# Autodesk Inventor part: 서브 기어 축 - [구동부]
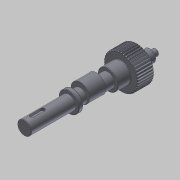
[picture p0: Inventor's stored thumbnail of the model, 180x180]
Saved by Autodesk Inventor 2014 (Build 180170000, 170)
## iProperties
Created: 2018-12
Part Number: 서브 기어 축 - [구동부]
Material: 강철, 연강
Document SubType Name: Modeling
Designer: mduedu
Categories: <?xml version="1.0" encoding="UTF-16"?> <MemberInstance><Categories><FamilyTemplate><FamilyTemplateParameter ValueType="xs:double" Id="1" ObjectReferenceKey="da
Density: 7.86 g/cm^3
Appearance: Steel
Mass: 514.759 g
Surface Area: 160.366 cm^2
Volume: 65.491 cm^3
Author: mduedu
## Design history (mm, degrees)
sketch "Sketch1"
  geometry: C1 r 21.3 at (0, 0)
  constraints: 1 centre point
  dimensions: "d0" = 42.6 diameter of C1 (= da_da)
extrude "Extrusion1" new body sketch "Sketch1" distance "d1" = 20 (= da_b); taper "d2" = 0 deg
workplane "Work Plane2"
sketch "Sketch2"
  geometry: C1 r 21.3 at (0, 0) reference; C2 r 20.5 at (0, 0)
  constraints: 1 centre point, 1 coincident
  dimensions: "d3" = 41 diameter of C2 (= da_dw)
feature "피치 지름" sketch "Sketch2" dims "d4" = 10, "d5" = 0
workplane "Work Plane8"
workplane "Work Plane9"
chamfer "모따기1" distance "d49" = 1; stored, may be unused: second distance "d50" = 2, angle "d51" = 45 deg
sketch "스케치3"
  geometry: C1 r 12.5 at (0, 0); 1 further point
  constraints: 1 centre point, 1 coincident
  dimensions: "d52" = 25 diameter of C1
extrude "돌출2" join sketch "스케치3" distance "d53" = 16; taper "d54" = 0 deg
sketch "스케치4"
  geometry: C1 r 8.5 at (0, 0); 1 further point
  constraints: 1 centre point, 1 coincident
  dimensions: "d55" = 17 diameter of C1
extrude "돌출3" join sketch "스케치4" distance "d56" = 103; taper "d57" = 0 deg
sketch "스케치5"
  geometry: C1 r 7.5 at (0, 0); 1 further point
  constraints: 1 centre point, 1 coincident
  dimensions: "d58" = 15 diameter of C1
extrude "돌출4" join sketch "스케치5" distance "d59" = 16; taper "d60" = 0 deg
sketch "스케치6"
  geometry: C1 r 4 at (0, 0); 1 further point
  constraints: 1 centre point, 1 coincident
  dimensions: "d61" = 8 diameter of C1
extrude "돌출5" join sketch "스케치6" distance "d62" = 7; taper "d63" = 0 deg
chamfer "모따기2" distance "d64" = 0.5; stored, may be unused: second distance "d65" = 2, angle "d66" = 45 deg
fillet "모깎기1" dims "d67" = 0.5
feature "스퍼 기어" dims "da_b" = 20, "da_d" = 41, "da_aw" = 31, "da_da" = 42.6, "da_df" = 39.086, "da_dw" = 41, angle "da_beta" = 0 deg, "da_lefttooth" = 0, "da_righttooth" = 0
node "작업 평면11"
sketch "스케치7"
  geometry: C1 r 11.5 at (0, 3); C2 r 8.5 at (0, 0) reference; 1 further point
  constraints: 1 centre point, 1 tangent, 1 vertical alignment
  dimensions: "d69" = 3 distance of point (0, 0) C1.centre; "d70" = 23 diameter of C1 (derived)
extrude "돌출6" join sketch "스케치7" stored distance "d71" = 20; taper "d72" = 0 deg
node "작업 평면12"
sketch "스케치8"
  geometry: C1 r 12.5 at (0, 0) reference; C2 r 12.5 at (0, 0) reference; 1 further point
extrude "돌출7" join sketch "스케치8" distance "d74" = 5; taper "d75" = 0 deg
chamfer "모따기3" distance "d76" = 0.5; stored, may be unused: second distance "d77" = 2, angle "d78" = 45 deg
sketch "스케치9"
  geometry: L1 (-8, 139)-(8, 139) reference; L2 (0, 139)-(0, 0); L3 (-8.5, 84)-(-8.5, 138.5) reference; L4 (-8.5, 115)-(0, 115); L5 (-8.5, 115)-(-8.5, 113.5); L6 (-8.5, 113.5)-(-7, 115); L7 (-7, 115)-(-8.5, 115)
  constraints: 10 end point, 4 point on line, 2 perpendicular, 1 collinear, 1 midpoint
  dimensions: "d79" = 24 distance between parallel lines of L4 L1; "d80" = 3 diameter of L5.end L4; "d81" = 45 deg angle of L6 L3
revolve "회전1" sketch "스케치9" stored, may be unused: angle "d82" = 90 deg
sketch "스케치10"
  geometry: L1 (-8.5, 116.5)-(-7, 115) reference; L2 (-8.5, 113.5)-(-7, 115) reference; 2 further points
  constraints: 1 coincident
node "작업점1"
node "작업 평면13"
sketch "스케치11"
  geometry: L1 (-2.5, 93.5)-(-2.5, 80.5); L2 (2.5, 80.5)-(2.5, 93.5); L3 (-8, 103)-(8, 103) reference; A1 r 2.5 centre (0, 93.5) between (2.5, 93.5) and (-2.5, 93.5); A2 r 2.5 centre (0, 80.5) between (-2.5, 80.5) and (2.5, 80.5); 1 further point
  constraints: 4 end point, 4 point on circle, 4 tangent, 2 centre point, 2 vertical alignment, 1 parallel
  dimensions: "d83" = 7 distance edge to line of A1 L3; "d84" = 18 dimension on A2 A1; "d85" = 5 distance between parallel lines of L1 L2
extrude "돌출8" cut sketch "스케치11" distance "d86" = 3; taper "d87" = 0 deg
sketch "스케치12" dims "d88" = 32
  geometry: C1 r 0.5 at (0, -16); 2 further points
  constraints: 2 vertical alignment, 1 centre point, 1 coincident, 2 other
  dimensions: "d89" = 1 diameter of C1
extrude "돌출9" join sketch "스케치12" distance "d90" = 0.3; taper "d91" = 0 deg
sketch "스케치13"
  geometry: C1 r 11.5 at (0, 3) reference; 1 further point
  node "절단 모서리 투영1"
body "Solid1"
body "Srf1"
node "투영된 루프1"
other parameters: "d16" = 31 (= da_aw), "d17" = 0, "d34" = 0.76624 (computed from da_z), "d39" = 0, "d41" = 0, "d43" = 31 (= da_aw), "d46" = 31 (= da_aw), "d47" = 0, "d48" = 0, "d68" = 24, "d73" = 48
